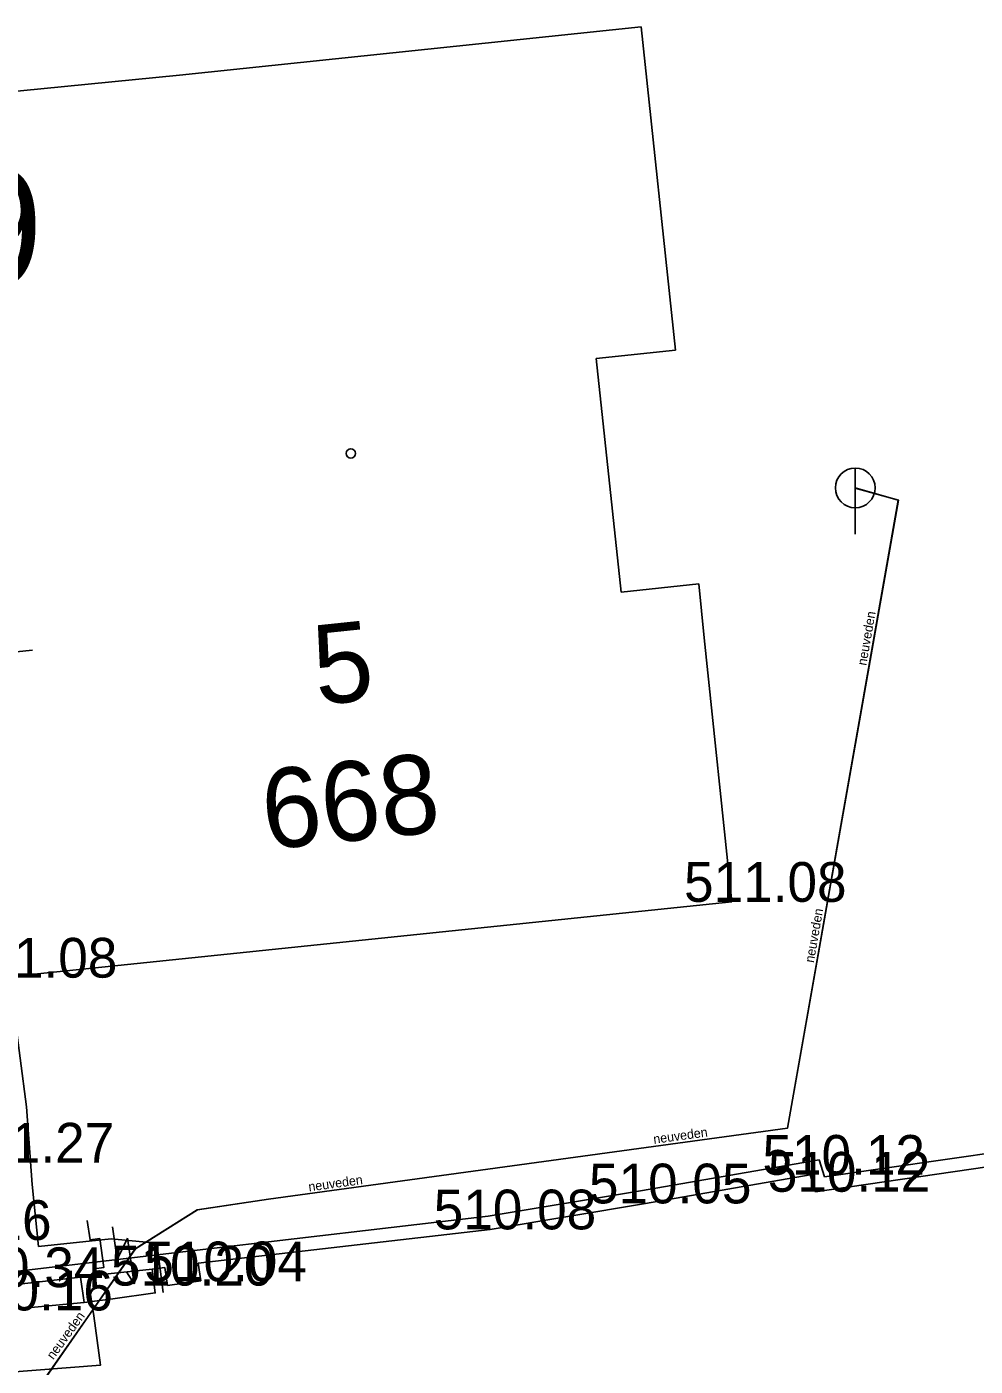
# Model space of a CAD drawing. Extents: x -669642 to -669119, y -1131006 to -1130466.
# Drawn here: x -669432.6 to -669414.71, y -1130545.11 to -1130519.84 of the extents above; entities that cross this region are included whole.
import ezdxf

# ---------------------------------------------------------------- set-up
doc = ezdxf.new("R2010")
doc.units = 0
for name, color, linetype in [('G_Bod_tecka', 7, 'Continuous'), ('G_Bod_vyska', 7, 'Continuous'), ('G_Budovy-znacky', 7, 'Continuous'), ('G_Budovy_Objekty', 7, 'Continuous'), ('G_Cesty_Schody', 7, 'Continuous'), ('G_Cisla_orientacni', 7, 'Continuous'), ('G_Cisla_popisna', 7, 'Continuous'), ('G_Ploty', 7, 'Continuous'), ('G_Site-kanalizace', 7, 'Continuous'), ('G_Site-Rozvadece', 7, 'Continuous'), ('G_Z_KANAL_podz_priblizne', 7, 'Continuous'), ('G_Z_PLYNY_podz_geodeticky', 7, 'Continuous'), ('G_Z_SPOJE_podz_geodeticky', 7, 'Continuous'), ('G_Z_SPOJE_podz_kotovane', 7, 'Continuous'), ('G_Z_SPOJE_podz_priblizne', 7, 'Continuous'), ('Vrstva 17', 7, 'Continuous'), ('Vrstva 3', 7, 'Continuous'), ('Vrstva 4', 7, 'Continuous')]:
    doc.layers.add(name, color=color, linetype=linetype)

msp = doc.modelspace()

# ---------------------------------------------------------------- linework, layer by layer
at = {"layer": 'G_Bod_tecka'}
for p, q in [((-669419.3, -1130536.35), (-669419.3, -1130536.35)), ((-669417.82, -1130541.5), (-669417.82, -1130541.5)), ((-669420.93, -1130542.04), (-669420.93, -1130542.04)), ((-669417.72, -1130541.82), (-669417.72, -1130541.82)), ((-669423.86, -1130542.53), (-669423.86, -1130542.53)), ((-669429.32, -1130543.51), (-669429.32, -1130543.51)), ((-669429.95, -1130543.59), (-669429.95, -1130543.59))]:
    msp.add_line(p, q, dxfattribs=at)
at = {"layer": 'G_Budovy-znacky'}
msp.add_circle((-669426.489, -1130527.89), 0.0875, dxfattribs=at)
at = {"layer": 'G_Budovy_Objekty'}
for p, q in [((-669421.01, -1130519.84), (-669429.72, -1130520.75)), ((-669420.36, -1130525.94), (-669421.01, -1130519.84)), ((-669429.72, -1130520.75), (-669434.7, -1130521.24)), ((-669421.86, -1130526.1), (-669420.36, -1130525.94)), ((-669421.39, -1130530.51), (-669421.86, -1130526.1)), ((-669419.92, -1130530.35), (-669421.39, -1130530.51)), ((-669419.82, -1130531.37), (-669419.92, -1130530.35)), ((-669419.82, -1130531.37), (-669419.3, -1130536.35)), ((-669419.3, -1130536.35), (-669433.07, -1130537.78))]:
    msp.add_line(p, q, dxfattribs=at)
at = {"layer": 'G_Cesty_Schody'}
msp.add_line((-669431.52, -1130543.91), (-669433.13, -1130544.06), dxfattribs=at)
at = {"layer": 'G_Ploty'}
for p, q in [((-669409.1, -1130540.32), (-669417.55, -1130541.54)), ((-669417.72, -1130541.82), (-669409.07, -1130540.57)), ((-669417.65, -1130541.22), (-669421.02, -1130541.8)), ((-669417.55, -1130541.54), (-669417.65, -1130541.22)), ((-669420.93, -1130542.04), (-669417.82, -1130541.5)), ((-669417.82, -1130541.5), (-669417.72, -1130541.82)), ((-669421.02, -1130541.8), (-669423.9, -1130542.28)), ((-669423.86, -1130542.53), (-669420.93, -1130542.04)), ((-669423.9, -1130542.28), (-669429.39, -1130542.92)), ((-669429.37, -1130543.17), (-669423.86, -1130542.53)), ((-669429.39, -1130542.92), (-669432.93, -1130543.34)), ((-669430.24, -1130543.28), (-669430, -1130543.25)), ((-669430, -1130543.25), (-669429.95, -1130543.59)), ((-669429.37, -1130543.17), (-669429.32, -1130543.5)), ((-669433.08, -1130543.6), (-669431.59, -1130543.43)), ((-669429.95, -1130543.59), (-669429.32, -1130543.5))]:
    msp.add_line(p, q, dxfattribs=at)
at = {"layer": 'G_Site-kanalizace'}
msp.add_line((-669416.97, -1130528.165), (-669416.97, -1130529.415), dxfattribs=at)
msp.add_circle((-669416.97, -1130528.54), 0.375, dxfattribs=at)
at = {"layer": 'G_Site-Rozvadece'}
for p, q in [((-669432.493, -1130531.6), (-669433.117, -1130531.662)), ((-669430.986, -1130542.481), (-669430.898, -1130543.101)), ((-669430.898, -1130543.101), (-669430.704, -1130542.694)), ((-669430.704, -1130542.694), (-669430.58, -1130543.56)), ((-669430.58, -1130543.56), (-669430.506, -1130543.302)), ((-669430.724, -1130543.333), (-669430.58, -1130543.56))]:
    msp.add_line(p, q, dxfattribs=at)
msp.add_lwpolyline([(-669431.28, -1130543.64), (-669431.331, -1130543.276), (-669431.15, -1130543.25), (-669431.228, -1130542.703), (-669431.409, -1130542.728), (-669431.462, -1130542.364)], dxfattribs=at)
msp.add_lwpolyline([(-669431.59, -1130543.43), (-669431.52, -1130543.91), (-669430.98, -1130543.84), (-669430.18, -1130543.73), (-669430.24, -1130543.28), (-669431.07, -1130543.37)], close=True, dxfattribs=at)
at = {"layer": 'G_Z_KANAL_podz_priblizne'}
msp.add_lwpolyline([(-669416.97, -1130528.54), (-669416.16, -1130528.77), (-669418.25, -1130540.62), (-669428.04, -1130541.96), (-669429.39, -1130542.16), (-669430.56, -1130542.9), (-669432.29, -1130545.39), (-669435.46, -1130548.38), (-669438.4, -1130549.62), (-669443.08, -1130550.84), (-669445.95, -1130550.92)], dxfattribs=at)
at = {"layer": 'G_Z_PLYNY_podz_geodeticky'}
msp.add_lwpolyline([(-669435.437, -1130544.98), (-669434.94, -1130545.01), (-669434.01, -1130545.1), (-669432.99, -1130545.23), (-669431.21, -1130545.09), (-669431.34, -1130544.16), (-669431.41, -1130543.72)], dxfattribs=at)
at = {"layer": 'G_Z_SPOJE_podz_geodeticky'}
msp.add_lwpolyline([(-669434.4, -1130529.64), (-669434.29, -1130531.12), (-669433.9, -1130534.5), (-669433.39, -1130537.73), (-669432.85, -1130538.38), (-669432.61, -1130540.22), (-669432.5, -1130541.68), (-669432.38, -1130542.85), (-669431.01, -1130542.71), (-669430.15, -1130542.79), (-669430.03, -1130543.72)], dxfattribs=at)
at = {"layer": 'G_Z_SPOJE_podz_kotovane'}
msp.add_lwpolyline([(-669434.4, -1130529.64), (-669434.29, -1130531.12), (-669433.9, -1130534.5), (-669433.39, -1130537.73), (-669432.85, -1130538.38), (-669432.61, -1130540.22), (-669432.5, -1130541.68), (-669432.38, -1130542.85), (-669431.01, -1130542.71), (-669430.15, -1130542.79), (-669430.03, -1130543.72)], dxfattribs=at)
at = {"layer": 'G_Z_SPOJE_podz_priblizne'}
msp.add_lwpolyline([(-669434.4, -1130529.64), (-669434.29, -1130531.12), (-669433.9, -1130534.5), (-669433.39, -1130537.73), (-669432.85, -1130538.38), (-669432.61, -1130540.22), (-669432.5, -1130541.68), (-669432.38, -1130542.85), (-669431.01, -1130542.71), (-669430.15, -1130542.79), (-669430.03, -1130543.72)], dxfattribs=at)
at = {"layer": 'Vrstva 17'}
msp.add_lwpolyline([(-669416.97, -1130528.544), (-669416.157, -1130528.774), (-669418.249, -1130540.622), (-669428.042, -1130541.962), (-669429.385, -1130542.159), (-669430.555, -1130542.9), (-669432.295, -1130545.386), (-669435.463, -1130548.379), (-669438.403, -1130549.624), (-669443.085, -1130550.836), (-669445.949, -1130550.925)], dxfattribs=at)
msp.add_lwpolyline([(-669416.97, -1130528.544), (-669416.157, -1130528.774), (-669418.249, -1130540.622), (-669428.042, -1130541.962), (-669429.385, -1130542.159), (-669430.555, -1130542.9), (-669432.295, -1130545.386), (-669435.463, -1130548.379), (-669438.403, -1130549.624), (-669443.085, -1130550.836), (-669445.949, -1130550.925)], dxfattribs=at)

# ---------------------------------------------------------------- texts
at = {"layer": 'G_Bod_vyska'}
for s, p in [('511.08', (-669420.202, -1130536.35)), ('511.08', (-669433.962, -1130537.78)), ('511.27', (-669434.021, -1130541.27)), ('510.12', (-669418.722, -1130541.5)), ('510.05', (-669421.996, -1130542.04)), ('510.12', (-669418.622, -1130541.82)), ('510.08', (-669424.926, -1130542.53)), ('511.16', (-669435.203, -1130542.73)), ('510.04', (-669430.386, -1130543.51)), ('510.34', (-669434.224, -1130543.62)), ('510.20', (-669431.016, -1130543.59)), ('510.16', (-669434.046, -1130544.06))]:
    msp.add_text(s, height=0.75, dxfattribs=at).set_placement(p)
at = {"layer": 'G_Cisla_orientacni'}
msp.add_text('5', height=1.5, rotation=5.952, dxfattribs=at).set_placement((-669427.12, -1130532.64))
at = {"layer": 'G_Cisla_popisna'}
msp.add_text('668', height=1.5, rotation=5.952, dxfattribs=at).set_placement((-669428.091, -1130535.368))
at = {"layer": 'Vrstva 3'}
for rotation, p in [(79.9937, (-669416.763, -1130531.9)), (79.9649, (-669417.753, -1130537.507)), (7.8258, (-669420.769, -1130540.916)), (7.8548, (-669427.277, -1130541.815)), (54.1254, (-669432.102, -1130544.999))]:
    msp.add_text('neuveden', height=0.1755, rotation=rotation, dxfattribs=at).set_placement(p)
at = {"layer": 'Vrstva 4'}
msp.add_text('1649', height=2.1939, dxfattribs=at).set_placement((-669438.827, -1130524.728))

doc.saveas('drawing.dxf')
